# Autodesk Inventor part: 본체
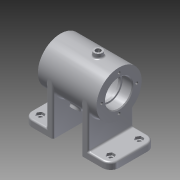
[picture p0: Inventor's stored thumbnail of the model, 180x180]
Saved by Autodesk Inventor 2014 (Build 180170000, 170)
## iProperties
Created: 2017-02
Part Number: 본체
Material: 알루미늄 6061
Document SubType Name: Modeling
Designer: user
Density: 2.71 g/cm^3
Appearance: 알루미늄 - 평지
Mass: 356.284 g
Surface Area: 422.453 cm^2
Volume: 131.47 cm^3
Author: user
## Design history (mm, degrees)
sketch "스케치1"
  geometry: C1 r 27 at (0, 0); 1 further point
  constraints: 1 centre point, 1 coincident
  dimensions: "d0" = 54 diameter of C1
extrude "돌출1" new body sketch "스케치1" stored distance "d1" = 70; taper "d2" = 0 deg
node "작업 평면1"
sketch "스케치2"
  geometry: L1 (27, 52)-(-27, 52); L2 (-27, 52)-(-27, 17); L3 (-27, 17)-(27, 17); L4 (27, 17)-(27, 52); L5 (27, 52)-(-27, 17); L6 (-27, 52)-(27, 17); 2 further points
  constraints: 12 end point, 2 midpoint, 2 parallel, 1 horizontal, 1 perpendicular
  dimensions: "d5" = 52 distance from line of point (0, 0) L1; "d6" = 17 distance from line of point (0, 0) L3; "d7" = 54 distance between parallel lines of L2 L4
extrude "돌출2" join sketch "스케치2" distance "d8" = 8; taper "d9" = 0 deg
sketch "스케치3"
  geometry: L1 (-8, 0)-(-8, 54) reference; L2 (-60, 0)-(-8, 0); L3 (-60, 54)-(-8, 54); L4 (0, 0)-(0, 54) reference; A1 r 27 centre (-60, 27) between (-60, 0) and (-60, 54) reference; A2 r 27 centre (-60, 27) between (-60, 0) and (-60, 54); 1 further point
  constraints: 4 end point, 4 point on circle, 2 tangent, 1 centre point, 1 coincident, 1 concentric, 1 parallel, 1 perpendicular
  dimensions: "d50" = 60 distance from line of point (-60, 27) L4 (derived); "d51" = 8 distance between parallel lines of L1 L4 (derived)
extrude "돌출3" join sketch "스케치3" distance "d10" = 8; taper "d11" = 0 deg
sketch "스케치4"
  geometry: L1 (0, -35)-(0, 35); L2 (-16, -35)-(-16, -23.3); L3 (-15.7, -23)-(-14, -23); L4 (-14, -23)-(-14, -20); L5 (-14, -20)-(-19, -20); L6 (-22, -17)-(-22, 17); L7 (-19, 20)-(-14, 20); L8 (-14, 20)-(-14, 23); L9 (-14, 23)-(-15.7, 23); L10 (-16, 23.3)-(-16, 35); L11 (27, 35)-(-27, 35) reference; L12 (-27, -35)-(27, -35) reference; L13 (-16, 35)-(0, 35); L14 (-16, -35)-(0, -35); A1 r 3 centre (-19, -17) between (-22, -17) and (-19, -20); A2 r 3 centre (-19, 17) between (-19, 20) and (-22, 17); A3 r 0.3 centre (-15.7, -23.3) between (-15.7, -23) and (-16, -23.3); A4 r 0.3 centre (-15.7, 23.3) between (-16, 23.3) and (-15.7, 23); 2 further points
  constraints: 24 end point, 8 point on circle, 8 tangent, 6 parallel, 4 centre point, 2 equal radius, 2 perpendicular, 2 point on line, 1 coincident, 1 collinear, 1 midpoint, 1 vertical
  dimensions: "d12" = 70 distance of L1.start L1.end; "d13" = 12 distance between parallel lines of L3 L12; "d14" = 12 distance between parallel lines of L9 L11; "d15" = 40 distance between parallel lines of L7 L5; "d17" = 3 distance between parallel lines of L3 L5; "d18" = 3 distance between parallel lines of L9 L7 (derived); "d19" = 32 diameter of L2 L1; "d20" = 32 diameter of L10 L1; "d21" = 28 diameter of L8 L1; "d22" = 28 diameter of L4 L1; "d23" = 44 diameter of L6 L1; "d24" = 3 radius of A1; "d25" = 0.3 radius of A3
revolve "회전1" sketch "스케치4" stored, may be unused: angle "d26" = 90 deg
chamfer "모따기1" distance "d27" = 1; stored, may be unused: second distance "d28" = 2, angle "d29" = 45 deg
sketch "스케치5"
  geometry: L1 (0, 21)-(0, -21); L2 (21, 0)-(-21, 0); C1 r 17 at (0, 0) reference; A1 r 21 centre (0, 0) between (0, 21) and (21, 0)
  constraints: 4 end point, 4 point on circle, 1 centre point, 1 coincident, 1 perpendicular, 1 vertical
  dimensions: "d30" = 42 diameter of A1; "d31" = 42 distance of L2.start L2.end; "d32" = 42 distance of L1.start L1.end
hole "구멍1" sketch "스케치5" at (0, 21), (21, 0), (0, -21), (-21, 0) diameter "d33" = 3.242; stored, may be unused: countersink angle "d37" = 90 deg, drill point angle "d39" = 118 deg; dims "d34" = 8, "d35" = 4, "d36" = 2, "d38" = 10
node "작업 평면2"
node "작업 평면4"
sketch "스케치8"
  geometry: L1 (0, 0)-(-25.16, -16.339); L2 (-60, 27)-(-60, -27) reference; L3 (0, 0)-(-60, 0)
  constraints: 4 end point, 1 midpoint
  dimensions: "d53" = 30 distance of L1.start L1.end; "d54" = 33 deg angle of L1 L3
node "작업 평면3"
sketch "스케치9"
  geometry: C1 r 6 at (0, 0); 1 further point
  constraints: 1 centre point, 1 coincident
  dimensions: "d55" = 12 diameter of C1
extrude "돌출6" join sketch "스케치9" stored distance "d56" = 5; taper "d57" = 0 deg
sketch "스케치10"
  geometry: C1 r 6 at (0, 0) reference; C2 r 3 at (0, 0)
  constraints: 1 centre point, 1 coincident
  dimensions: "d58" = 6 diameter of C2
extrude "돌출7" cut sketch "스케치10" distance "d59" = 20; taper "d60" = 0 deg
feature "스레드2" dims "d61" = 10, "d62" = 0
fillet "모깎기2" dims "d63" = 2
fillet "모깎기3" dims "d64" = 10
fillet "모깎기4" dims "d65" = 10
sketch "스케치11"
  geometry: L1 (45, -27)-(45, 27) reference; C1 r 5 at (20, 0); 1 further point
  constraints: 1 centre point, 1 horizontal alignment
  dimensions: "d66" = 10 diameter of C1; "d67" = 25 distance from line of C1.centre L1
extrude "돌출8" join sketch "스케치11" stored distance "d68" = 20; taper "d69" = 0 deg
sketch "스케치12"
  geometry: C1 r 5 at (0, 0) reference; C2 r 3 at (0, 0); 1 further point
  constraints: 1 centre point, 1 coincident
  dimensions: "d70" = 6 diameter of C2
extrude "돌출9" cut sketch "스케치12" distance "d71" = 15; taper "d72" = 0 deg
fillet "모깎기5" dims "d73" = 2
feature "스레드3" dims "d74" = 10, "d75" = 0
node "작업 평면5"
sketch "스케치13"
  geometry: L1 (-79, -10)-(-79, 60) reference; L2 (-79, -10)-(-25, -10) reference; 2 further points
  constraints: 1 other
  dimensions: "d76" = 27 distance from line of L1 point (-52, 25); "d77" = 35 distance from line of point (-52, 25) L2
feature "엠보싱1" sketch "스케치13" dims "d0" = 54, "d78" = 0.5, "d79" = 0
sketch "스케치14" dims "d80" = 9, "d81" = 9
  geometry: L1 (21.5, 10)-(19.25, 6.103); L2 (19.25, 6.103)-(14.75, 6.103); L3 (14.75, 6.103)-(12.5, 10); L4 (12.5, 10)-(14.75, 13.897); L5 (14.75, 13.897)-(19.25, 13.897); L6 (19.25, 13.897)-(21.5, 10); L7 (21.5, 44)-(19.25, 40.103); L8 (19.25, 40.103)-(14.75, 40.103); L9 (14.75, 40.103)-(12.5, 44); L10 (12.5, 44)-(14.75, 47.897); L11 (14.75, 47.897)-(19.25, 47.897); L12 (19.25, 47.897)-(21.5, 44); A1 r 10 centre (17, 44) between (27, 44) and (17, 54) reference; A2 r 10 centre (17, 10) between (17, 0) and (27, 10) reference; 5 further points
  constraints: 24 end point, 4 coincident, 2 horizontal alignment, 30 other
  dimensions: "d82" = 3.89711 vertical distance of L2.end L3.end; "d83" = 3.89711 vertical distance of L8.end L9.end
extrude "돌출10" cut sketch "스케치14" distance "d84" = 3; taper "d85" = 0 deg
sketch "스케치15"
  geometry: C1 r 2.5 at (-25, 44); C2 r 2.5 at (-25, 10); A1 r 10 centre (-25, 44) between (-25, 54) and (-35, 44) reference; A2 r 10 centre (-25, 10) between (-35, 10) and (-25, 0) reference; 1 further point
  constraints: 2 centre point, 2 coincident
  dimensions: "d86" = 5 diameter of C1; "d87" = 5 diameter of C2
extrude "돌출11" cut sketch "스케치15" distance "d88" = 8; taper "d89" = 0 deg
fillet "모깎기6" dims "d90" = 2
fillet "모깎기7" dims "d91" = 2
fillet "모깎기8" dims "d92" = 2
fillet "모깎기9" dims "d93" = 2
node "솔리드1"
mirror "대칭1"
mirror "대칭2"
mirror "대칭3"
other parameters: "d40" = -92
